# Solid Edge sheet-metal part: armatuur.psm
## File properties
Author: Blackblade
Template: Normal.psm
Last saved by: Blackblade
Revision: 12
Application: Solid Edge
Accuracy: 0.990
Material Thickness: 1.00 mm
Bend Radius: 1.00 mm
Relief Width: 1.00 mm
Relief Length: 0.00 mm
Neutral Factor: 0.330
Minimum Arc Length: 0.10 mm
Deviational Tolerance: 0.10 mm
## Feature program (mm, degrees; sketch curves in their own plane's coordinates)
base tab "unnamed BaseTab 1"
louver "Louver_1"  LouverHeight = 2 mm
louver "Louver_2"  LouverDepth = 4 mm; LouverHeight = 2 mm
louver "Louver_3"  LouverDepth = 4 mm; LouverHeight = 2 mm
bead "unnamed Bead 1"
dimple "Dimple_1"
mirror "unnamed Mirror 1" of "Dimple_1"
pattern "unnamed Pattern 1"
mirror "unnamed Mirror 2" of "Dimple_1"
pattern "unnamed Pattern 2"
mirror "unnamed Mirror 3" of "unnamed Pattern 2"
pattern "unnamed Pattern 3"
dimple "Dimple_2"
dimple "Dimple_4"
sketch for "ExtrudedCutout_1" plane through (0, -6.0508, 2) normal (0, 0, 1) x-axis (1, 0, 0)
  circle centre (11.0985, 2.0213) radius 0.2932
extrude "ExtrudedCutout_1" cut
pattern "unnamed Pattern 4" of "ExtrudedCutout_1"
extrude "unnamed Cutout 1" cut
extrude "unnamed Cutout 2" cut
extrude "unnamed Cutout 3" cut
extrude "unnamed Cutout 4" cut
extrude "unnamed Cutout 5" cut
extrude "unnamed Cutout 6" cut
extrude "unnamed Cutout 7" cut
sketch for "unnamed Cutout 8" plane through (0, 0, 1) normal (0, 0, 1) x-axis (-1, 0, 0)
  line (67.1383, -22.4282) -> (68.8701, 6.4696)
  bspline degree 3 poles (68.8701, 6.4696) (68.2599, 11.4847) (67.4996, 16.4821) (66.5503, 21.4581) knots 0 1 multiplicities 4 4
  line (66.5503, 21.4581) -> (-66.5503, 21.4581)
  bspline degree 3 poles (-66.5503, 21.4581) (-67.4996, 16.4821) (-68.2599, 11.4847) (-68.8701, 6.4696) knots 0 1 multiplicities 4 4
  line (-68.8701, 6.4696) -> (-67.1383, -22.4282)
extrude "unnamed Cutout 8" cut
sketch for "ExtrudedCutout_18" plane through (0, 0.3474, 1) normal (0, 0, 1) x-axis (-1, 0, 0)
  circle centre (0, -6.8713) radius 2.5
extrude "ExtrudedCutout_18" cut
dimple "unnamed Dimple 1"
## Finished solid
Body 1: solid body, 151 faces, 350 edges, 210 vertices.
  Faces by surface: cylinder 69, plane 47, sphere 12, torus 12, cone 8, swept 3
  Edges by curve: line 186, circle 110, ellipse 40, intersection 8, spline 6
Bounding box of the edges (mm; curved faces can reach further): 137.740 x 43.611 x 4.000, from (-68.8701, -21.4581, -1) to (68.8701, 22.1529, 3).
Cylindrical faces by radius (mm): R0.2932 x8, R1 x52, R2.5 x1, R4 x3, R5 x3, R20.5093 x1, R21.5093 x1
Conical faces (half-angle, radius in mm at the cone's reference point): 15 deg R0.3014 x2, 15 deg R0.6363 x2, 15 deg R1.2673 x2, 15 deg R1.6023 x2
Toroidal faces (ring radius, tube radius in mm): R0.5 r1 x4, R1.6023 r1 x4, R18.5093 r1 x1, R19.5093 r1 x1, R20.5093 r1 x1, R21.5093 r1 x1
Spherical faces by radius (mm): R4 x6, R5 x6
Planar faces by outward normal: +x 2, +y 6, +z 10, -x 2, -y 7, -z 10, oblique 10
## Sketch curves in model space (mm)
line (-28.2035, 4.3471, 1) -> (-28.2035, 9.3471, 1)
line (-28.2035, 9.3471, 1) -> (-24.2035, 9.3471, 1)
line (-24.2035, 9.3471, 1) -> (-24.2035, 4.3471, 1)
line (-24.2035, 4.3471, 1) -> (-28.2035, 4.3471, 1)
circle centre (0, 7.2188, 1) radius 2.5
spline (67.1548, 22.1529, 0) -> (0, 10.7719, 0) -> (-67.1548, 22.1529, 0)
line (68.8701, -6.4696, 1) -> (67.1383, 22.4282, 1)
spline (66.5503, -21.4581, 1) -> (67.8373, -13.9785, 1) -> (68.8701, -6.4696, 1)
line (-67.1383, 22.4282, 1) -> (-68.8701, -6.4696, 1)
spline (-68.8701, -6.4696, 1) -> (-67.8373, -13.9785, 1) -> (-66.5503, -21.4581, 1)
line (-66.5503, -21.4581, 1) -> (66.5503, -21.4581, 1)
circle centre (11.0985, -4.0295, 2) radius 0.2932
arc centre (0, 9.4078, 3) radius 19.5093 from (15.8265, -2, 3) through (0, -10.1016, 3) to (-15.8265, -2, 3)
line (-15.8265, -2, 3) -> (15.8265, -2, 3)
arc centre (0, 9.4078, 1) radius 21.5093 from (19.3428, 0, 1) through (0, -12.1016, 1) to (-19.3428, 0, 1)
line (-19.3428, 0, 1) -> (19.3428, 0, 1)
line (54.3938, -3.172, 1) -> (34.3938, -3.172, 1)
line (34.3938, -3.172, 1) -> (34.3938, -8.172, 1)
line (34.3938, -8.172, 1) -> (54.3938, -8.172, 1)
line (54.3938, -8.172, 1) -> (54.3938, -3.172, 1)
line (-23.5956, -14.9945, 1) -> (-23.5956, 0, 1)
line (23.9257, -14.9945, 1) -> (23.9257, 0, 1)
spline (68.1365, 22.4881, 1) -> (0, 10.7719, 1) -> (-68.1365, 22.4881, 1)
spline (-69.8737, -6.5003, 0) -> (-68.7671, -14.5088, 0) -> (-67.37, -22.4881, 0)
line (-67.37, -22.4881, 0) -> (67.37, -22.4881, 0)
spline (67.37, -22.4881, 0) -> (68.7671, -14.5088, 0) -> (69.8737, -6.5003, 0)
line (69.8737, -6.5003, 0) -> (68.1365, 22.4881, 0)
spline (-68.1365, 22.4881, 0) -> (0, 10.7719, 0) -> (68.1365, 22.4881, 0)
line (-68.1365, 22.4881, 0) -> (-69.8737, -6.5003, 0)
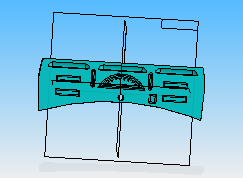
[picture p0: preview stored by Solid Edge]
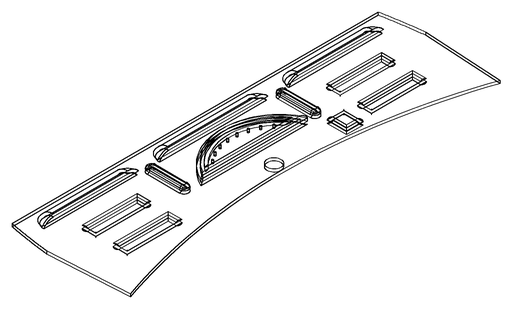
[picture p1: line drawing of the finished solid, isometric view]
